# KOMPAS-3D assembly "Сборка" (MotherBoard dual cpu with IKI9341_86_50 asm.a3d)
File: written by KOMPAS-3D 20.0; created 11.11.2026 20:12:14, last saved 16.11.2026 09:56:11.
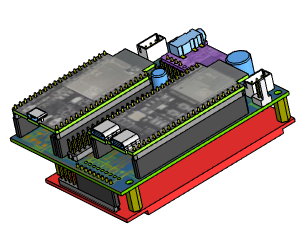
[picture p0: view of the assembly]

Document properties: Полное имя файла: D:\RicWork\Project-EPS32\box_compas\сборки компонентов\MotherBoard dual cpu with IKI9341_86_50 asm.a3d

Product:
- Part/product: Сборка
    Масса: 0.272217
  - Component [assembly]: Сборка  | Масса: 0.183959; source file: MotherBoard dual cpu asm.a3d
  - Component [assembly]: Сборка  | Масса: 0.0882585; source file: ..\монитор\ILI9341_86_50 asm+ 9pin v2.a3d

Referenced files in D:\RicWork\Project-EPS32\box_compas\сборки компонентов\: MotherBoard dual cpu asm.a3d
Referenced files in D:\RicWork\Project-EPS32\box_compas\монитор\: ILI9341_86_50 asm+ 9pin v2.a3d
